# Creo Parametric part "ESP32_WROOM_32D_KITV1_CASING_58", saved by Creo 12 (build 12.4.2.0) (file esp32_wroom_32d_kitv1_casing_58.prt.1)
Units: Custom; MM, KILOGRAM, SECS

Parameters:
  PTC_WM_ITERATION = "0"
  PTC_WM_VERSION = "-.0"
  PTC_WM_LIFECYCLE_STATE = "In Work"
  PTC_WM_LIFECYCLE = "MO_CADDocument"
  PTC_WM_CREATED_BY = "Maximilian Roepper (Z0017RMS: MO)"
  PTC_WM_CREATED_ON = "18-Sep-26 11:36:42 AM"
  PTC_WM_MODIFIED_BY = "Maximilian Roepper (Z0017RMS: MO)"
  PTC_WM_MODIFIED_ON = "18-Sep-26 11:36:46 AM"
  PDMLINKNUMBER = "PDM000071455154"
  PTC_WM_NAME = "esp32_wroom_32d_kitv1_casing_58.prt"
  PTC_WM_NUMBER = "PDM000071455154"

Other parameters: WEIGHT, WEIGHT_FACTOR, WEIGHT_ADD, _MASS_TEMP, _DIFF_TEMP, MC_ERRORS, SUPPLIER

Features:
  1. coordinate system
  2. datum plane "PRT_YZ"
  3. datum plane "PRT_XY"
  4. datum plane "PRT_XZ"
  5. coordinate system
  6. datum axis
  7. datum axis
  8. datum axis
  9. coordinate system
  10. imported feature
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
Other named items: PRT, SIEMENS_MO, DRW_VIEW_ORG, PRT_X, PRT_Y, PRT_Z, CS0, ROUGH_GROB

Layers: 00_STD_CSYS-KSYS, 01_STD_PLANES-EBENEN, 02_STD_AXES-ACHSEN, 03_STD_CSYS-KSYS, 24_IMPORT_FEAT-IMPORT_KE

Surfaces: 5 plane, 1 cylinder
